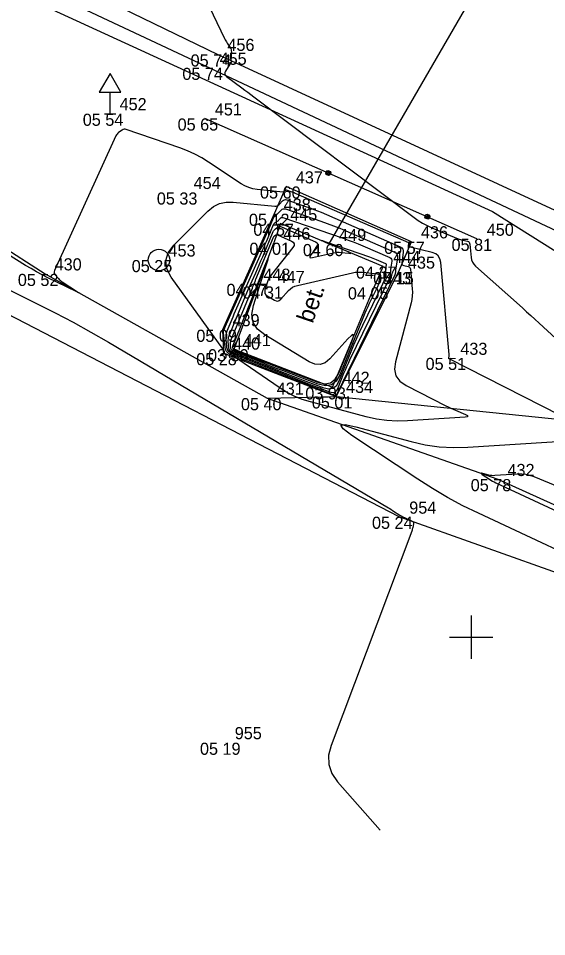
# Model space of a CAD drawing. Extents: x -711234 to -710007, y -1026313 to -1025448.
# Drawn here: x -711060.46 to -711048.26, y -1025906.92 to -1025885.71 of the extents above; entities that cross this region are included whole.
import ezdxf

# ---------------------------------------------------------------- set-up
doc = ezdxf.new("R2010")
doc.units = 0
for name, color, linetype in [('Ex_Major Contours', 7, 'Continuous'), ('Ex_Minor Contours', 7, 'Continuous'), ('Z_betonova_konstrukce', 7, 'Continuous'), ('Z_body', 7, 'Continuous'), ('Z_body_cisla', 7, 'Continuous'), ('Z_body_vysky_redukovane', 7, 'Continuous'), ('Z_dopravni_znacky', 7, 'Continuous'), ('Z_hektometricka_sit', 7, 'Continuous'), ('Z_hrany_paty', 7, 'Continuous'), ('Z_katastr_hranice', 7, 'Continuous'), ('Z_komunikace', 7, 'Continuous'), ('Z_pole_rozhranni', 7, 'Continuous'), ('Z_popisy', 7, 'Continuous'), ('Z_propustek', 7, 'Continuous'), ('Z_vdz25_plna', 7, 'Continuous'), ('Z_zabradli', 7, 'Continuous'), ('Z_zabradli_znaky', 7, 'Continuous'), ('Z_zelen_jednotliva', 7, 'Continuous')]:
    doc.layers.add(name, color=color, linetype=linetype)

# ---------------------------------------------------------------- blocks, each defined once
blk = doc.blocks.new('POINT_DISPLAY')
blk.add_line((0, 0), (0, 0))
blk = doc.blocks.new('Z10001')
blk.add_circle((0, 0), 0.25)
blk = doc.blocks.new('Z530')
for p, q in [((-0.05, 0.03), (-0.03, 0.05)), ((-0.05, -0.03), (-0.05, 0.03)), ((-0.03, 0.05), (0.03, 0.05)), ((-0.03, -0.03), (-0.03, 0.03)), ((-0.03, 0.03), (0.03, 0.03)), ((-0.03, -0.03), (0.03, 0.03)), ((0.03, 0.05), (0.05, 0.03)), ((0.03, 0.03), (0.03, -0.03)), ((0.05, 0.03), (0.05, -0.03)), ((-0.03, -0.05), (-0.05, -0.03)), ((0.03, -0.03), (-0.03, -0.03)), ((0.03, -0.05), (-0.03, -0.05)), ((0.05, -0.03), (0.03, -0.05))]:
    blk.add_line(p, q)
blk = doc.blocks.new('Z527')
for p, q in [((0, 0.93), (-0.25, 0.5)), ((0.25, 0.5), (0, 0.93)), ((-0.25, 0.5), (0.25, 0.5)), ((0, 0), (0, 0.5)), ((-0.13, 0), (0.13, 0))]:
    blk.add_line(p, q)

msp = doc.modelspace()

# ---------------------------------------------------------------- linework, layer by layer
at = {"layer": 'Ex_Major Contours'}
for points in [[(-711054.553, -1025890.297), (-711054.55, -1025890.293), (-711054.547, -1025890.29), (-711054.543, -1025890.287), (-711054.526, -1025890.276), (-711054.522, -1025890.273), (-711054.518, -1025890.27), (-711054.514, -1025890.266), (-711054.51, -1025890.263), (-711054.389, -1025890.136), (-711054.366, -1025890.117), (-711054.342, -1025890.107), (-711054.315, -1025890.105), (-711054.287, -1025890.111), (-711053.469, -1025890.392), (-711053.324, -1025890.444), (-711053.18, -1025890.498), (-711053.036, -1025890.556), (-711052.894, -1025890.616), (-711051.782, -1025891.1), (-711051.742, -1025891.124), (-711051.716, -1025891.156), (-711051.703, -1025891.195), (-711051.703, -1025891.242), (-711051.745, -1025891.527), (-711051.747, -1025891.545), (-711051.75, -1025891.563), (-711051.754, -1025891.6), (-711051.756, -1025891.609), (-711051.758, -1025891.617), (-711051.761, -1025891.626), (-711051.764, -1025891.634), (-711053.108, -1025894.408), (-711053.112, -1025894.417), (-711053.119, -1025894.433), (-711053.12, -1025894.435), (-711053.121, -1025894.436), (-711053.123, -1025894.437), (-711053.125, -1025894.436), (-711053.144, -1025894.429), (-711055.558, -1025893.469), (-711055.609, -1025893.441), (-711055.647, -1025893.404), (-711055.672, -1025893.357), (-711055.685, -1025893.3), (-711055.717, -1025892.971), (-711055.718, -1025892.951), (-711055.716, -1025892.932), (-711055.712, -1025892.913), (-711055.706, -1025892.894), (-711055.676, -1025892.821), (-711055.668, -1025892.802), (-711055.661, -1025892.784), (-711055.653, -1025892.765), (-711055.645, -1025892.747), (-711054.634, -1025890.487), (-711054.625, -1025890.468), (-711054.617, -1025890.449), (-711054.608, -1025890.429), (-711054.6, -1025890.41), (-711054.555, -1025890.302)], [(-711055.507, -1025893.271), (-711055.509, -1025893.281), (-711055.51, -1025893.291), (-711055.51, -1025893.301), (-711055.506, -1025893.342), (-711055.504, -1025893.351), (-711055.5, -1025893.359), (-711055.493, -1025893.365), (-711055.485, -1025893.37), (-711055.187, -1025893.488), (-711055.134, -1025893.509), (-711055.081, -1025893.53), (-711055.028, -1025893.55), (-711054.975, -1025893.57), (-711053.539, -1025894.114), (-711053.379, -1025894.149), (-711053.246, -1025894.126), (-711053.138, -1025894.044), (-711053.056, -1025893.903), (-711052.757, -1025893.17), (-711052.719, -1025893.059), (-711052.722, -1025893.012), (-711052.765, -1025893.03), (-711052.849, -1025893.112), (-711053.267, -1025893.571), (-711053.375, -1025893.662), (-711053.491, -1025893.703), (-711053.613, -1025893.696), (-711053.742, -1025893.641), (-711054.769, -1025893.022), (-711054.935, -1025892.889), (-711055.033, -1025892.731), (-711055.064, -1025892.547), (-711055.027, -1025892.338), (-711054.742, -1025891.443), (-711054.692, -1025891.279), (-711054.68, -1025891.222), (-711054.707, -1025891.273), (-711054.772, -1025891.432), (-711055.221, -1025892.564), (-711055.25, -1025892.636), (-711055.279, -1025892.707), (-711055.308, -1025892.779), (-711055.337, -1025892.851), (-711055.504, -1025893.261)]]:
    msp.add_lwpolyline(points, close=True, dxfattribs=at)
at = {"layer": 'Ex_Minor Contours'}
for points in [[(-711056.139, -1025885.249), (-711055.694, -1025886.174), (-711055.68, -1025886.201), (-711055.666, -1025886.227), (-711055.651, -1025886.253), (-711055.635, -1025886.278), (-711055.568, -1025886.378), (-711055.554, -1025886.404), (-711055.544, -1025886.431), (-711055.539, -1025886.459), (-711055.538, -1025886.488), (-711055.547, -1025886.674), (-711055.547, -1025886.677), (-711055.546, -1025886.68), (-711055.545, -1025886.683), (-711055.544, -1025886.685), (-711055.538, -1025886.696), (-711055.537, -1025886.699), (-711055.536, -1025886.702), (-711055.537, -1025886.704), (-711055.538, -1025886.707), (-711055.672, -1025886.926), (-711055.688, -1025886.962), (-711055.689, -1025886.996), (-711055.676, -1025887.026), (-711055.648, -1025887.053), (-711055.299, -1025887.311), (-711055.229, -1025887.363), (-711055.159, -1025887.415), (-711055.089, -1025887.467), (-711055.02, -1025887.519), (-711051.317, -1025890.311), (-711051.22, -1025890.379), (-711051.12, -1025890.441), (-711051.015, -1025890.496), (-711050.907, -1025890.545), (-711050.298, -1025890.797), (-711050.273, -1025890.807), (-711050.247, -1025890.816), (-711050.221, -1025890.824), (-711050.194, -1025890.831), (-711050.088, -1025890.857), (-711050.064, -1025890.866), (-711050.047, -1025890.88), (-711050.035, -1025890.9), (-711050.029, -1025890.925), (-711050.001, -1025891.23), (-711049.991, -1025891.288), (-711049.97, -1025891.34), (-711049.94, -1025891.388), (-711049.9, -1025891.43), (-711048.817, -1025892.398), (-711048.72, -1025892.485), (-711048.623, -1025892.573), (-711048.527, -1025892.66), (-711048.431, -1025892.748), (-711048.047, -1025893.101)], [(-711047.939, -1025894.88), (-711050.506, -1025893.576), (-711050.513, -1025893.571), (-711050.518, -1025893.565), (-711050.519, -1025893.558), (-711050.518, -1025893.55), (-711050.508, -1025893.513), (-711050.506, -1025893.504), (-711050.505, -1025893.495), (-711050.505, -1025893.486), (-711050.505, -1025893.476), (-711050.703, -1025891.344), (-711050.722, -1025891.261), (-711050.76, -1025891.196), (-711050.819, -1025891.148), (-711050.898, -1025891.118), (-711051.41, -1025890.992), (-711051.418, -1025890.988), (-711051.424, -1025890.983), (-711051.427, -1025890.975), (-711051.427, -1025890.966), (-711051.421, -1025890.924), (-711051.421, -1025890.914), (-711051.424, -1025890.906), (-711051.429, -1025890.9), (-711051.437, -1025890.895), (-711054.041, -1025889.761), (-711054.064, -1025889.751), (-711054.088, -1025889.741), (-711054.112, -1025889.732), (-711054.137, -1025889.724), (-711054.267, -1025889.679), (-711054.275, -1025889.677), (-711054.282, -1025889.678), (-711054.288, -1025889.681), (-711054.294, -1025889.685), (-711054.317, -1025889.709), (-711054.323, -1025889.714), (-711054.33, -1025889.718), (-711054.337, -1025889.72), (-711054.345, -1025889.72), (-711054.94, -1025889.662), (-711055.04, -1025889.646), (-711055.136, -1025889.618), (-711055.227, -1025889.579), (-711055.315, -1025889.528), (-711056.067, -1025889.027), (-711056.224, -1025888.929), (-711056.385, -1025888.843), (-711056.552, -1025888.767), (-711056.725, -1025888.701), (-711057.965, -1025888.274), (-711057.989, -1025888.268), (-711058.013, -1025888.268), (-711058.035, -1025888.275), (-711058.057, -1025888.287), (-711058.142, -1025888.346), (-711058.162, -1025888.362), (-711058.179, -1025888.381), (-711058.194, -1025888.401), (-711058.206, -1025888.423), (-711059.621, -1025891.534), (-711059.629, -1025891.56), (-711059.63, -1025891.584), (-711059.623, -1025891.608), (-711059.608, -1025891.63), (-711059.534, -1025891.718), (-711059.515, -1025891.74), (-711059.494, -1025891.759), (-711059.472, -1025891.777), (-711059.448, -1025891.793), (-711059.113, -1025892.007), (-711059.065, -1025892.038), (-711059.051, -1025892.051), (-711059.07, -1025892.046), (-711059.121, -1025892.021), (-711059.777, -1025891.699), (-711059.908, -1025891.632), (-711060.037, -1025891.562), (-711060.164, -1025891.489), (-711060.29, -1025891.413), (-711066.072, -1025887.783)], [(-711061.886, -1025891.382), (-711060.023, -1025892.299), (-711059.605, -1025892.51), (-711059.19, -1025892.729), (-711058.781, -1025892.955), (-711058.375, -1025893.19), (-711051.911, -1025897.013), (-711051.881, -1025897.031), (-711051.851, -1025897.05), (-711051.822, -1025897.068), (-711051.792, -1025897.088), (-711051.644, -1025897.187), (-711051.631, -1025897.195), (-711051.617, -1025897.203), (-711051.604, -1025897.21), (-711051.59, -1025897.217), (-711051.505, -1025897.256), (-711051.477, -1025897.269), (-711051.366, -1025897.321), (-711051.349, -1025897.331), (-711051.338, -1025897.345), (-711051.333, -1025897.362), (-711051.334, -1025897.382), (-711051.35, -1025897.468), (-711051.354, -1025897.489), (-711051.359, -1025897.51), (-711051.366, -1025897.531), (-711051.373, -1025897.551), (-711053.235, -1025902.505), (-711053.291, -1025902.731), (-711053.284, -1025902.946), (-711053.215, -1025903.15), (-711053.083, -1025903.343), (-711052.103, -1025904.463)], [(-711048.005, -1025897.992), (-711048.37, -1025897.822), (-711049.831, -1025897.141), (-711050.193, -1025896.965), (-711050.547, -1025896.774), (-711050.894, -1025896.571), (-711051.233, -1025896.354), (-711052.755, -1025895.34), (-711052.956, -1025895.19), (-711053.009, -1025895.107), (-711052.912, -1025895.091), (-711052.666, -1025895.143), (-711051.382, -1025895.485), (-711051.06, -1025895.557), (-711050.735, -1025895.602), (-711050.407, -1025895.621), (-711050.077, -1025895.613), (-711047.037, -1025895.42)], [(-711044.243, -1025898.081), (-711048.548, -1025896.301), (-711048.641, -1025896.269), (-711048.735, -1025896.247), (-711048.832, -1025896.237), (-711048.93, -1025896.238), (-711049.455, -1025896.271), (-711049.49, -1025896.272), (-711049.525, -1025896.27), (-711049.56, -1025896.265), (-711049.594, -1025896.257), (-711049.732, -1025896.221), (-711049.758, -1025896.215), (-711049.769, -1025896.217), (-711049.763, -1025896.226), (-711049.742, -1025896.242), (-711049.58, -1025896.349), (-711049.543, -1025896.373), (-711049.505, -1025896.395), (-711049.466, -1025896.416), (-711049.427, -1025896.436), (-711044.031, -1025898.949)]]:
    msp.add_lwpolyline(points, dxfattribs=at)
for points in [[(-711051.711, -1025895.01), (-711051.95, -1025894.996), (-711052.188, -1025894.963), (-711052.423, -1025894.91), (-711053.708, -1025894.569), (-711053.9, -1025894.509), (-711054.084, -1025894.433), (-711054.261, -1025894.343), (-711054.432, -1025894.236), (-711055.368, -1025893.594), (-711055.4, -1025893.574), (-711055.433, -1025893.555), (-711055.467, -1025893.538), (-711055.502, -1025893.523), (-711055.695, -1025893.446), (-711055.704, -1025893.441), (-711055.711, -1025893.435), (-711055.715, -1025893.427), (-711055.717, -1025893.417), (-711055.721, -1025893.376), (-711055.723, -1025893.365), (-711055.726, -1025893.356), (-711055.73, -1025893.346), (-711055.735, -1025893.338), (-711056.926, -1025891.684), (-711057.029, -1025891.49), (-711057.053, -1025891.303), (-711056.999, -1025891.121), (-711056.867, -1025890.947), (-711056.08, -1025890.159), (-711055.952, -1025890.055), (-711055.813, -1025889.986), (-711055.661, -1025889.95), (-711055.497, -1025889.95), (-711054.532, -1025890.044), (-711054.504, -1025890.044), (-711054.479, -1025890.038), (-711054.455, -1025890.026), (-711054.434, -1025890.008), (-711054.354, -1025889.924), (-711054.333, -1025889.907), (-711054.31, -1025889.897), (-711054.286, -1025889.895), (-711054.259, -1025889.901), (-711053.803, -1025890.058), (-711053.718, -1025890.088), (-711053.634, -1025890.12), (-711053.55, -1025890.153), (-711053.467, -1025890.188), (-711051.642, -1025890.984), (-711051.604, -1025891.006), (-711051.579, -1025891.036), (-711051.567, -1025891.073), (-711051.567, -1025891.117), (-711051.601, -1025891.352), (-711051.601, -1025891.375), (-711051.594, -1025891.394), (-711051.58, -1025891.407), (-711051.558, -1025891.416), (-711051.456, -1025891.441), (-711051.434, -1025891.45), (-711051.417, -1025891.463), (-711051.406, -1025891.482), (-711051.401, -1025891.505), (-711051.359, -1025891.953), (-711051.355, -1025892.036), (-711051.359, -1025892.119), (-711051.369, -1025892.201), (-711051.387, -1025892.282), (-711051.749, -1025893.64), (-711051.771, -1025893.814), (-711051.737, -1025893.963), (-711051.648, -1025894.088), (-711051.504, -1025894.188), (-711050.582, -1025894.656), (-711050.527, -1025894.683), (-711050.471, -1025894.71), (-711050.415, -1025894.736), (-711050.358, -1025894.762), (-711050.13, -1025894.862), (-711050.088, -1025894.884), (-711050.076, -1025894.901), (-711050.093, -1025894.913), (-711050.14, -1025894.92), (-711051.47, -1025895.004)], [(-711054.558, -1025890.458), (-711054.55, -1025890.446), (-711054.539, -1025890.435), (-711054.527, -1025890.426), (-711054.471, -1025890.389), (-711054.46, -1025890.382), (-711054.45, -1025890.374), (-711054.44, -1025890.365), (-711054.431, -1025890.356), (-711054.395, -1025890.318), (-711054.386, -1025890.311), (-711054.376, -1025890.307), (-711054.365, -1025890.306), (-711054.353, -1025890.308), (-711052.954, -1025890.789), (-711052.838, -1025890.83), (-711052.724, -1025890.873), (-711052.61, -1025890.918), (-711052.498, -1025890.966), (-711051.881, -1025891.235), (-711051.856, -1025891.249), (-711051.84, -1025891.269), (-711051.833, -1025891.292), (-711051.833, -1025891.32), (-711051.852, -1025891.455), (-711051.856, -1025891.479), (-711051.859, -1025891.503), (-711051.862, -1025891.528), (-711051.866, -1025891.552), (-711051.878, -1025891.649), (-711051.882, -1025891.673), (-711051.887, -1025891.696), (-711051.895, -1025891.719), (-711051.905, -1025891.741), (-711052.807, -1025893.604), (-711052.844, -1025893.681), (-711052.879, -1025893.759), (-711052.913, -1025893.837), (-711052.946, -1025893.915), (-711053.09, -1025894.269), (-711053.119, -1025894.319), (-711053.157, -1025894.348), (-711053.204, -1025894.356), (-711053.261, -1025894.344), (-711053.504, -1025894.252), (-711053.564, -1025894.229), (-711053.625, -1025894.205), (-711053.685, -1025894.182), (-711053.746, -1025894.158), (-711055.54, -1025893.444), (-711055.58, -1025893.422), (-711055.61, -1025893.392), (-711055.63, -1025893.355), (-711055.64, -1025893.31), (-711055.659, -1025893.116), (-711055.661, -1025893.068), (-711055.657, -1025893.02), (-711055.647, -1025892.974), (-711055.632, -1025892.928), (-711055.498, -1025892.6), (-711055.47, -1025892.53), (-711055.44, -1025892.461), (-711055.41, -1025892.392), (-711055.38, -1025892.323), (-711054.808, -1025891.044), (-711054.781, -1025890.985), (-711054.755, -1025890.925), (-711054.73, -1025890.865), (-711054.704, -1025890.805), (-711054.565, -1025890.472)], [(-711053.558, -1025890.895), (-711053.539, -1025890.925), (-711053.542, -1025890.96), (-711053.565, -1025891.001), (-711053.701, -1025891.172), (-711053.725, -1025891.208), (-711053.726, -1025891.23), (-711053.705, -1025891.239), (-711053.663, -1025891.233), (-711053.178, -1025891.122), (-711053.134, -1025891.114), (-711053.091, -1025891.11), (-711053.047, -1025891.109), (-711053.002, -1025891.113), (-711052.825, -1025891.135), (-711052.792, -1025891.138), (-711052.779, -1025891.135), (-711052.788, -1025891.126), (-711052.819, -1025891.112), (-711053.362, -1025890.884), (-711053.44, -1025890.85), (-711053.465, -1025890.837), (-711053.437, -1025890.843), (-711053.357, -1025890.87), (-711052.346, -1025891.217), (-711052.307, -1025891.231), (-711052.267, -1025891.246), (-711052.229, -1025891.262), (-711052.19, -1025891.278), (-711051.979, -1025891.37), (-711051.971, -1025891.375), (-711051.965, -1025891.381), (-711051.962, -1025891.389), (-711051.963, -1025891.399), (-711051.969, -1025891.441), (-711051.972, -1025891.462), (-711051.974, -1025891.483), (-711052.001, -1025891.698), (-711052.008, -1025891.737), (-711052.017, -1025891.775), (-711052.03, -1025891.812), (-711052.046, -1025891.848), (-711052.507, -1025892.8), (-711052.578, -1025892.951), (-711052.648, -1025893.103), (-711052.714, -1025893.257), (-711052.779, -1025893.411), (-711053.062, -1025894.105), (-711053.119, -1025894.203), (-711053.193, -1025894.259), (-711053.286, -1025894.275), (-711053.396, -1025894.251), (-711053.872, -1025894.071), (-711053.991, -1025894.025), (-711054.11, -1025893.98), (-711054.229, -1025893.933), (-711054.347, -1025893.886), (-711055.521, -1025893.419), (-711055.551, -1025893.403), (-711055.573, -1025893.381), (-711055.588, -1025893.354), (-711055.595, -1025893.321), (-711055.609, -1025893.178), (-711055.611, -1025893.142), (-711055.608, -1025893.107), (-711055.601, -1025893.073), (-711055.589, -1025893.039), (-711055.298, -1025892.324), (-711055.26, -1025892.231), (-711055.22, -1025892.138), (-711055.18, -1025892.046), (-711055.14, -1025891.953), (-711054.975, -1025891.586), (-711054.934, -1025891.493), (-711054.894, -1025891.401), (-711054.854, -1025891.309), (-711054.815, -1025891.216), (-711054.571, -1025890.632), (-711054.562, -1025890.614), (-711054.551, -1025890.598), (-711054.537, -1025890.584), (-711054.522, -1025890.572), (-711054.454, -1025890.527), (-711054.437, -1025890.519), (-711054.419, -1025890.515), (-711054.401, -1025890.516), (-711054.383, -1025890.521), (-711053.597, -1025890.87)], [(-711054.108, -1025890.88), (-711054.087, -1025890.914), (-711054.09, -1025890.954), (-711054.116, -1025890.999), (-711054.611, -1025891.621), (-711054.64, -1025891.661), (-711054.664, -1025891.702), (-711054.685, -1025891.746), (-711054.702, -1025891.791), (-711054.762, -1025891.98), (-711054.769, -1025892.022), (-711054.763, -1025892.06), (-711054.743, -1025892.093), (-711054.709, -1025892.12), (-711054.545, -1025892.219), (-711054.505, -1025892.236), (-711054.468, -1025892.238), (-711054.432, -1025892.225), (-711054.399, -1025892.197), (-711054.215, -1025891.995), (-711054.171, -1025891.954), (-711054.123, -1025891.92), (-711054.07, -1025891.895), (-711054.013, -1025891.877), (-711052.743, -1025891.585), (-711052.681, -1025891.574), (-711052.618, -1025891.568), (-711052.554, -1025891.567), (-711052.491, -1025891.572), (-711052.168, -1025891.613), (-711052.142, -1025891.62), (-711052.125, -1025891.633), (-711052.117, -1025891.653), (-711052.116, -1025891.679), (-711052.131, -1025891.797), (-711052.136, -1025891.826), (-711052.143, -1025891.855), (-711052.152, -1025891.883), (-711052.164, -1025891.91), (-711052.352, -1025892.298), (-711052.387, -1025892.372), (-711052.421, -1025892.446), (-711052.454, -1025892.521), (-711052.485, -1025892.596), (-711053.033, -1025893.941), (-711053.118, -1025894.086), (-711053.229, -1025894.171), (-711053.367, -1025894.195), (-711053.531, -1025894.158), (-711054.357, -1025893.846), (-711054.476, -1025893.8), (-711054.596, -1025893.754), (-711054.715, -1025893.708), (-711054.834, -1025893.661), (-711055.503, -1025893.394), (-711055.522, -1025893.384), (-711055.536, -1025893.37), (-711055.546, -1025893.353), (-711055.551, -1025893.331), (-711055.56, -1025893.239), (-711055.561, -1025893.216), (-711055.559, -1025893.194), (-711055.554, -1025893.172), (-711055.547, -1025893.15), (-711055.053, -1025891.938), (-711055.039, -1025891.904), (-711055.026, -1025891.87), (-711054.998, -1025891.801), (-711054.991, -1025891.784), (-711054.984, -1025891.767), (-711054.977, -1025891.75), (-711054.97, -1025891.733), (-711054.565, -1025890.763), (-711054.561, -1025890.755), (-711054.556, -1025890.747), (-711054.549, -1025890.74), (-711054.541, -1025890.734), (-711054.508, -1025890.712), (-711054.5, -1025890.708), (-711054.491, -1025890.706), (-711054.482, -1025890.707), (-711054.473, -1025890.709), (-711054.152, -1025890.852)]]:
    msp.add_lwpolyline(points, close=True, dxfattribs=at)
at = {"layer": 'Z_betonova_konstrukce'}
for p, q in [((-711054.27, -1025889.59), (-711054.55, -1025890.22)), ((-711051.38, -1025890.87), (-711054.27, -1025889.59)), ((-711054.55, -1025890.22), (-711055.74, -1025892.9)), ((-711054.4, -1025890.45), (-711054.56, -1025890.89)), ((-711052.03, -1025891.44), (-711054.4, -1025890.45)), ((-711055.47, -1025893.35), (-711054.56, -1025890.89)), ((-711051.68, -1025891.57), (-711051.38, -1025890.87)), ((-711053.12, -1025894.44), (-711051.68, -1025891.57)), ((-711052.24, -1025891.92), (-711052.03, -1025891.44)), ((-711053.2, -1025894.23), (-711052.24, -1025891.92)), ((-711055.74, -1025892.9), (-711055.72, -1025893.44)), ((-711055.72, -1025893.44), (-711053.12, -1025894.44)), ((-711055.47, -1025893.35), (-711053.2, -1025894.23))]:
    msp.add_line(p, q, dxfattribs=at)
at = {"layer": 'Z_hektometricka_sit'}
for p, q in [((-711050, -1025899.5), (-711050, -1025900.5)), ((-711050.5, -1025900), (-711049.5, -1025900))]:
    msp.add_line(p, q, dxfattribs=at)
at = {"layer": 'Z_hrany_paty'}
for p, q in [((-711066.38, -1025887.42), (-711059.84, -1025891.61)), ((-711059.84, -1025891.61), (-711054.71, -1025894.48)), ((-711054.71, -1025894.48), (-711053.12, -1025894.44)), ((-711054.71, -1025894.48), (-711049.38, -1025896.35)), ((-711053.12, -1025894.44), (-711037.34, -1025896.06)), ((-711049.38, -1025896.35), (-711043, -1025899.25))]:
    msp.add_line(p, q, dxfattribs=at)
at = {"layer": 'Z_katastr_hranice'}
msp.add_lwpolyline([(-711143.66, -1025881.69), (-711119.52, -1025871.38), (-711081.1, -1025874.43), (-711069.6, -1025880.3), (-711060.15, -1025885.29), (-711049.51, -1025890.17), (-711031.09, -1025901.74), (-711010.7, -1025906.92), (-710992.71, -1025905.14), (-710973.48, -1025897.7)], dxfattribs=at)
at = {"layer": 'Z_komunikace'}
for p, q in [((-711064.43, -1025882.91), (-711056.04, -1025886.85)), ((-711056.04, -1025886.85), (-711046.39, -1025891.39))]:
    msp.add_line(p, q, dxfattribs=at)
at = {"layer": 'Z_pole_rozhranni'}
for p, q in [((-711051.66, -1025897.22), (-711064.25, -1025890.71)), ((-711041.66, -1025900.79), (-711051.66, -1025897.22))]:
    msp.add_line(p, q, dxfattribs=at)
at = {"layer": 'Z_propustek'}
for p, q in [((-711053.28, -1025890.92), (-711042.93, -1025873.02)), ((-711054.7, -1025891.9), (-711055.02, -1025891.84))]:
    msp.add_line(p, q, dxfattribs=at)
at = {"layer": 'Z_vdz25_plna'}
for p, q in [((-711064.17, -1025882.51), (-711055.85, -1025886.54)), ((-711055.85, -1025886.54), (-711046.16, -1025891.02))]:
    msp.add_line(p, q, dxfattribs=at)
at = {"layer": 'Z_zabradli'}
msp.add_line((-711049.87, -1025890.8), (-711056.15, -1025888.02), dxfattribs=at)

# ---------------------------------------------------------------- block references
at = {"layer": 'Z_body'}
for p in [(-711055.85, -1025886.54), (-711056.04, -1025886.85), (-711058.34, -1025887.91), (-711056.15, -1025888.02), (-711054.27, -1025889.59), (-711056.63, -1025889.73), (-711054.55, -1025890.22), (-711054.4, -1025890.45), (-711054.56, -1025890.89), (-711053.28, -1025890.92), (-711051.38, -1025890.87), (-711049.87, -1025890.8), (-711057.21, -1025891.29), (-711052.03, -1025891.44), (-711051.68, -1025891.57), (-711059.84, -1025891.61), (-711055.02, -1025891.84), (-711054.7, -1025891.9), (-711052.24, -1025891.92), (-711055.74, -1025892.9), (-711055.72, -1025893.44), (-711055.47, -1025893.35), (-711050.47, -1025893.55), (-711053.2, -1025894.23), (-711054.71, -1025894.48), (-711053.12, -1025894.44), (-711049.38, -1025896.35), (-711051.66, -1025897.22), (-711055.68, -1025902.44)]:
    msp.add_blockref('POINT_DISPLAY', p, dxfattribs=at)
at = {"layer": 'Z_dopravni_znacky'}
msp.add_blockref('Z527', (-711058.34, -1025887.91), dxfattribs=at)
at = {"layer": 'Z_zabradli_znaky', "rotation": -23.900000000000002}
for p in [(-711053.3, -1025889.28), (-711051.01, -1025890.29)]:
    msp.add_blockref('Z530', p, dxfattribs=at)
at = {"layer": 'Z_zelen_jednotliva'}
msp.add_blockref('Z10001', (-711057.21, -1025891.29), dxfattribs=at)

# ---------------------------------------------------------------- texts
at = {"layer": 'Z_body_cisla'}
for s, p in [('456', (-711055.63, -1025886.46)), ('455', (-711055.81, -1025886.78)), ('452', (-711058.12, -1025887.83)), ('451', (-711055.92, -1025887.95)), ('437', (-711054.05, -1025889.52)), ('454', (-711056.41, -1025889.65)), ('438', (-711054.33, -1025890.15)), ('445', (-711054.18, -1025890.38)), ('446', (-711054.34, -1025890.82)), ('436', (-711051.16, -1025890.79)), ('450', (-711049.64, -1025890.73)), ('449', (-711053.05, -1025890.85)), ('453', (-711056.99, -1025891.21)), ('444', (-711051.8, -1025891.36)), ('430', (-711059.62, -1025891.53)), ('435', (-711051.46, -1025891.49)), ('448', (-711054.8, -1025891.77)), ('447', (-711054.47, -1025891.82)), ('443', (-711052.01, -1025891.85)), ('439', (-711055.51, -1025892.82)), ('440', (-711055.5, -1025893.36)), ('441', (-711055.25, -1025893.28)), ('433', (-711050.25, -1025893.48)), ('442', (-711052.97, -1025894.15)), ('431', (-711054.49, -1025894.4)), ('434', (-711052.89, -1025894.36)), ('432', (-711049.16, -1025896.28)), ('954', (-711051.43, -1025897.15)), ('955', (-711055.46, -1025902.36))]:
    msp.add_text(s, height=0.28, dxfattribs=at).set_placement(p)
at = {"layer": 'Z_body_vysky_redukovane'}
for s, p in [('05 74', (-711056.48, -1025886.82)), ('05 74', (-711056.67, -1025887.13)), ('05 54', (-711058.97, -1025888.19)), ('05 65', (-711056.78, -1025888.3)), ('05 60', (-711054.877, -1025889.87)), ('05 33', (-711057.26, -1025890.01)), ('05 12', (-711055.133, -1025890.5)), ('04 57', (-711055.03, -1025890.73)), ('04 01', (-711055.12, -1025891.17)), ('04 60', (-711053.887, -1025891.2)), ('05 57', (-711052.01, -1025891.15)), ('05 81', (-711050.453, -1025891.08)), ('05 25', (-711057.84, -1025891.57)), ('04 37', (-711052.66, -1025891.72)), ('05 15', (-711052.263, -1025891.85)), ('05 52', (-711060.47, -1025891.89)), ('04 27', (-711055.65, -1025892.12)), ('04 31', (-711055.283, -1025892.18)), ('04 05', (-711052.847, -1025892.2)), ('05 09', (-711056.347, -1025893.18)), ('05 28', (-711056.35, -1025893.72)), ('03 80', (-711056.077, -1025893.63)), ('05 51', (-711051.053, -1025893.83)), ('03 93', (-711053.83, -1025894.51)), ('05 40', (-711055.317, -1025894.76)), ('05 01', (-711053.68, -1025894.72)), ('05 78', (-711050.01, -1025896.63)), ('05 24', (-711052.29, -1025897.5)), ('05 19', (-711056.263, -1025902.72))]:
    msp.add_text(s, height=0.28, dxfattribs=at).set_placement(p)
at = {"layer": 'Z_popisy'}
msp.add_text('bet.', height=0.4, rotation=71.1, dxfattribs=at).set_placement((-711053.66, -1025892.77))

doc.saveas('drawing.dxf')
